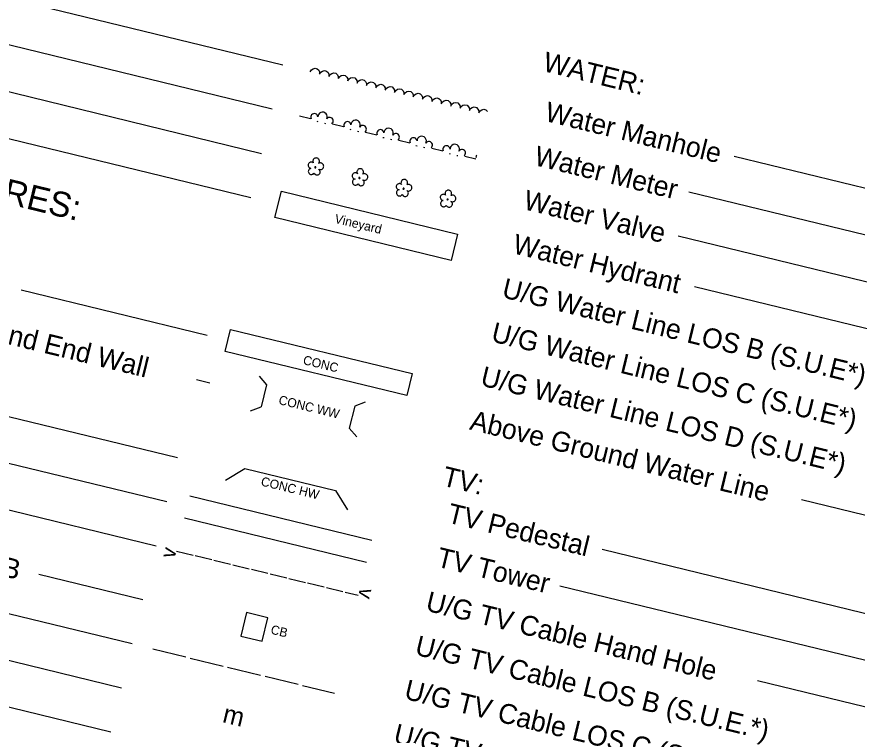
# Model space of a CAD drawing. Extents: x 1532568 to 1534465, y 472683 to 474150.
# Drawn here: x 1533832.3 to 1534202.9, y 473454 to 473770.7 of the extents above; entities that cross this region are included whole.
import ezdxf

# ---------------------------------------------------------------- set-up
doc = ezdxf.new("R2010")
doc.units = 0
doc.layers.add('Sheet Symbology CELL', color=7, linetype='Continuous')

msp = doc.modelspace()

# ---------------------------------------------------------------- linework, layer by layer
at = {"layer": 'Sheet Symbology CELL'}
for p, q in [((1533949.71, 473749.35), (1533743.06, 473799.65)), ((1533944.98, 473729.92), (1533769, 473772.75)), ((1533940.27, 473710.34), (1533741.14, 473758.81)), ((1533961.75, 473746.42), (1533962.27, 473747.27)), ((1533962.27, 473747.27), (1533963.01, 473747.76)), ((1533963.01, 473747.76), (1533963.89, 473748.01)), ((1533963.89, 473748.01), (1533964.81, 473747.79)), ((1533964.81, 473747.79), (1533965.47, 473747.11)), ((1533965.47, 473747.11), (1533965.85, 473746.35)), ((1533967.14, 473746.76), (1533968.02, 473747.01)), ((1533968.02, 473747.01), (1533968.94, 473746.78)), ((1533965.85, 473746.35), (1533965.85, 473745.48)), ((1533965.88, 473745.42), (1533966.4, 473746.27)), ((1533966.4, 473746.27), (1533967.14, 473746.76)), ((1533968.94, 473746.78), (1533969.6, 473746.11)), ((1533969.6, 473746.11), (1533969.98, 473745.34)), ((1533969.98, 473745.34), (1533969.97, 473744.47)), ((1533970.01, 473744.41), (1533970.53, 473745.26)), ((1533970.53, 473745.26), (1533971.26, 473745.75)), ((1533971.26, 473745.75), (1533972.15, 473746)), ((1533972.15, 473746), (1533973.07, 473745.78)), ((1533973.07, 473745.78), (1533973.73, 473745.1)), ((1533973.73, 473745.1), (1533974.11, 473744.34)), ((1533974.11, 473744.34), (1533974.1, 473743.47)), ((1533974.14, 473743.41), (1533974.66, 473744.26)), ((1533974.66, 473744.26), (1533975.39, 473744.75)), ((1533975.39, 473744.75), (1533976.28, 473745)), ((1533976.28, 473745), (1533977.2, 473744.77)), ((1533977.2, 473744.77), (1533977.86, 473744.1)), ((1533977.86, 473744.1), (1533978.24, 473743.33)), ((1533978.24, 473743.33), (1533978.23, 473742.46)), ((1533978.27, 473742.4), (1533978.79, 473743.25)), ((1533978.79, 473743.25), (1533979.52, 473743.74)), ((1533979.52, 473743.74), (1533980.41, 473743.99)), ((1533980.41, 473743.99), (1533981.33, 473743.77)), ((1533981.33, 473743.77), (1533981.99, 473743.09)), ((1533981.99, 473743.09), (1533982.37, 473742.33)), ((1533982.37, 473742.33), (1533982.36, 473741.46)), ((1533982.4, 473741.4), (1533982.92, 473742.25)), ((1533982.92, 473742.25), (1533983.65, 473742.74)), ((1533983.65, 473742.74), (1533984.54, 473742.98)), ((1533984.54, 473742.98), (1533985.46, 473742.76)), ((1533985.46, 473742.76), (1533986.12, 473742.09)), ((1533986.12, 473742.09), (1533986.5, 473741.32)), ((1533986.5, 473741.32), (1533986.49, 473740.45)), ((1533986.53, 473740.39), (1533987.05, 473741.24)), ((1533987.05, 473741.24), (1533987.78, 473741.73)), ((1533987.78, 473741.73), (1533988.67, 473741.98)), ((1533988.67, 473741.98), (1533989.59, 473741.76)), ((1533989.59, 473741.76), (1533990.25, 473741.08)), ((1533990.25, 473741.08), (1533990.63, 473740.32)), ((1533990.63, 473740.32), (1533990.62, 473739.45)), ((1533990.66, 473739.38), (1533991.18, 473740.24)), ((1533991.18, 473740.24), (1533991.91, 473740.73)), ((1533991.91, 473740.73), (1533992.8, 473740.97)), ((1533992.8, 473740.97), (1533993.72, 473740.75)), ((1533993.72, 473740.75), (1533994.38, 473740.07)), ((1533994.38, 473740.07), (1533994.76, 473739.31)), ((1533995.3, 473739.23), (1533996.04, 473739.72)), ((1533996.04, 473739.72), (1533996.92, 473739.97)), ((1533996.92, 473739.97), (1533997.85, 473739.74)), ((1533997.85, 473739.74), (1533998.51, 473739.07)), ((1533935.54, 473690.91), (1533736.41, 473739.38)), ((1533994.76, 473739.31), (1533994.75, 473738.44)), ((1533994.79, 473738.38), (1533995.3, 473739.23)), ((1533998.51, 473739.07), (1533998.89, 473738.31)), ((1533998.89, 473738.31), (1533998.88, 473737.43)), ((1533998.92, 473737.37), (1533999.43, 473738.23)), ((1533999.43, 473738.23), (1534000.17, 473738.72)), ((1534000.17, 473738.72), (1534001.05, 473738.96)), ((1534001.05, 473738.96), (1534001.98, 473738.74)), ((1534001.98, 473738.74), (1534002.64, 473738.06)), ((1534002.64, 473738.06), (1534003.02, 473737.3)), ((1534003.02, 473737.3), (1534003.01, 473736.43)), ((1534003.05, 473736.37), (1534003.56, 473737.22)), ((1534003.56, 473737.22), (1534004.3, 473737.71)), ((1534004.3, 473737.71), (1534005.18, 473737.96)), ((1534005.18, 473737.96), (1534006.11, 473737.73)), ((1534006.11, 473737.73), (1534006.77, 473737.06)), ((1534006.77, 473737.06), (1534007.15, 473736.3)), ((1534007.15, 473736.3), (1534007.14, 473735.42)), ((1534007.18, 473735.36), (1534007.69, 473736.22)), ((1534007.69, 473736.22), (1534008.43, 473736.71)), ((1534008.43, 473736.71), (1534009.31, 473736.95)), ((1534009.31, 473736.95), (1534010.24, 473736.73)), ((1534010.24, 473736.73), (1534010.9, 473736.05)), ((1534010.9, 473736.05), (1534011.28, 473735.29)), ((1534012.56, 473735.7), (1534013.44, 473735.95)), ((1534013.44, 473735.95), (1534014.37, 473735.72)), ((1534014.37, 473735.72), (1534015.02, 473735.05)), ((1534011.28, 473735.29), (1534011.27, 473734.42)), ((1534011.31, 473734.36), (1534011.82, 473735.21)), ((1534011.82, 473735.21), (1534012.56, 473735.7)), ((1534015.02, 473735.05), (1534015.41, 473734.29)), ((1534015.41, 473734.29), (1534015.4, 473733.41)), ((1534015.44, 473733.35), (1534015.95, 473734.21)), ((1534015.95, 473734.21), (1534016.69, 473734.7)), ((1534016.69, 473734.7), (1534017.57, 473734.94)), ((1534017.57, 473734.94), (1534018.5, 473734.72)), ((1534018.5, 473734.72), (1534019.15, 473734.04)), ((1534019.15, 473734.04), (1534019.53, 473733.28)), ((1534019.53, 473733.28), (1534019.53, 473732.41)), ((1534019.56, 473732.35), (1534020.08, 473733.2)), ((1534020.08, 473733.2), (1534020.82, 473733.69)), ((1534020.82, 473733.69), (1534021.7, 473733.94)), ((1534021.7, 473733.94), (1534022.62, 473733.71)), ((1534022.62, 473733.71), (1534023.28, 473733.04)), ((1534023.28, 473733.04), (1534023.66, 473732.28)), ((1534023.66, 473732.28), (1534023.66, 473731.4)), ((1534023.69, 473731.34), (1534024.21, 473732.2)), ((1534024.21, 473732.2), (1534024.95, 473732.69)), ((1534024.95, 473732.69), (1534025.83, 473732.93)), ((1534025.83, 473732.93), (1534026.75, 473732.71)), ((1534026.75, 473732.71), (1534027.41, 473732.03)), ((1534027.41, 473732.03), (1534027.79, 473731.27)), ((1534027.79, 473731.27), (1534027.79, 473730.4)), ((1534027.82, 473730.34), (1534028.34, 473731.19)), ((1534028.34, 473731.19), (1534029.08, 473731.68)), ((1534029.08, 473731.68), (1534029.96, 473731.93)), ((1534029.96, 473731.93), (1534030.88, 473731.7)), ((1534030.88, 473731.7), (1534031.54, 473731.03)), ((1534031.54, 473731.03), (1534031.92, 473730.27)), ((1534031.92, 473730.27), (1534031.92, 473729.39)), ((1534031.95, 473729.33), (1534032.47, 473730.19)), ((1534032.47, 473730.19), (1534033.21, 473730.68)), ((1534033.21, 473730.68), (1534034.09, 473730.92)), ((1534034.09, 473730.92), (1534035.01, 473730.7)), ((1534035.01, 473730.7), (1534035.67, 473730.02)), ((1534035.67, 473730.02), (1534036.05, 473729.26)), ((1534036.05, 473729.26), (1534036.05, 473728.39)), ((1534036.08, 473728.33), (1534036.6, 473729.18)), ((1534036.6, 473729.18), (1534037.34, 473729.67)), ((1534037.34, 473729.67), (1534038.22, 473729.92)), ((1534038.22, 473729.92), (1534039.14, 473729.69)), ((1534039.14, 473729.69), (1534039.8, 473729.02)), ((1534039.8, 473729.02), (1534039.84, 473728.96)), ((1533957.02, 473726.99), (1533961.88, 473725.81)), ((1533964.63, 473724.62), (1533965.11, 473724.5)), ((1533968.03, 473723.79), (1533968.52, 473723.68)), ((1533971.6, 473723.44), (1533976.46, 473722.26)), ((1533979.2, 473721.07), (1533979.69, 473720.96)), ((1533982.6, 473720.25), (1533983.09, 473720.13)), ((1533986.17, 473719.89), (1533991.03, 473718.71)), ((1533993.78, 473717.53), (1533994.26, 473717.41)), ((1533997.18, 473716.7), (1533997.66, 473716.58)), ((1534000.75, 473716.35), (1534005.6, 473715.16)), ((1534008.35, 473713.98), (1534008.84, 473713.86)), ((1534011.75, 473713.15), (1534012.24, 473713.03)), ((1534015.32, 473712.8), (1534020.18, 473711.62)), ((1534022.93, 473710.43), (1534023.41, 473710.31)), ((1534026.33, 473709.6), (1534026.81, 473709.49)), ((1534029.9, 473709.25), (1534034.75, 473708.07)), ((1534306.48, 473670.66), (1534148.7, 473709.07)), ((1534301.75, 473651.23), (1534128.76, 473693.34)), ((1534297.02, 473631.8), (1534124.03, 473673.9)), ((1534292.29, 473612.37), (1534131.21, 473651.57)), ((1533916.32, 473630.23), (1533834.29, 473650.19)), ((1533911.59, 473610.79), (1533917.41, 473609.38)), ((1533939.15, 473612.18), (1533942.46, 473608.43)), ((1533903.18, 473576.23), (1533778.52, 473606.57)), ((1533942.46, 473608.43), (1533940.1, 473598.71)), ((1533935.43, 473596.9), (1533940.1, 473598.71)), ((1533981.33, 473598.97), (1533978.96, 473589.25)), ((1533985.99, 473600.78), (1533981.33, 473598.97)), ((1533898.45, 473556.8), (1533733.09, 473597.05)), ((1533982.27, 473585.5), (1533978.96, 473589.25)), ((1533893.72, 473537.37), (1533715.45, 473580.76)), ((1533924.3, 473566.38), (1533932.85, 473571.58)), ((1533932.85, 473571.58), (1533972.93, 473561.83)), ((1533972.93, 473561.83), (1533978.13, 473553.28)), ((1533908.67, 473559.46), (1533988.83, 473539.95)), ((1534273.37, 473534.64), (1534178.43, 473557.74)), ((1533906.31, 473549.74), (1533986.47, 473530.23)), ((1534263.4, 473493.67), (1534090.41, 473535.78)), ((1533902.76, 473535.17), (1533910.05, 473533.39)), ((1533911.02, 473533.16), (1533918.3, 473531.38)), ((1533919.28, 473531.15), (1533926.56, 473529.37)), ((1533927.54, 473529.14), (1533934.82, 473527.36)), ((1533883.21, 473494.2), (1533750.15, 473526.59)), ((1533887.94, 473513.63), (1533842.08, 473524.79)), ((1533935.79, 473527.13), (1533943.08, 473525.35)), ((1533944.05, 473525.12), (1533951.34, 473523.34)), ((1533952.31, 473523.11), (1533959.6, 473521.33)), ((1533960.57, 473521.1), (1533967.86, 473519.32)), ((1533968.83, 473519.09), (1533976.12, 473517.31)), ((1533977.09, 473517.08), (1533982.92, 473515.66)), ((1534258.67, 473474.24), (1534071.79, 473519.73)), ((1533878.48, 473474.76), (1533766.09, 473502.12)), ((1533873.75, 473455.33), (1533714.21, 473494.16)), ((1533892.25, 473492), (1533906.83, 473488.45)), ((1533908.77, 473487.98), (1533923.34, 473484.43)), ((1533925.29, 473483.96), (1533939.86, 473480.41)), ((1533941.8, 473479.94), (1533956.38, 473476.39)), ((1534253.94, 473454.81), (1534159, 473477.91)), ((1533958.32, 473475.92), (1533972.41, 473472.49))]:
    msp.add_line(p, q, dxfattribs=at)
for points in [[(1533965.4, 473706.02), (1533965.62, 473706.28), (1533965.74, 473706.56), (1533965.76, 473706.86), (1533965.78, 473707.17), (1533965.7, 473707.45), (1533965.61, 473707.72), (1533965.41, 473707.98), (1533965.21, 473708.18), (1533964.89, 473708.36), (1533964.65, 473708.42), (1533964.34, 473708.44), (1533964.03, 473708.42), (1533963.75, 473708.33), (1533963.46, 473708.2), (1533963.24, 473707.94), (1533963.09, 473707.72), (1533962.97, 473707.44), (1533962.9, 473707.15), (1533962.87, 473706.85), (1533962.96, 473706.57), (1533963.08, 473706.23), (1533962.88, 473706.43), (1533962.6, 473706.55), (1533962.31, 473706.62), (1533962.04, 473706.59), (1533961.77, 473706.55), (1533961.48, 473706.41), (1533961.24, 473706.27), (1533961.04, 473706.06), (1533960.93, 473705.83), (1533960.8, 473705.5), (1533960.79, 473705.24), (1533960.82, 473704.98), (1533960.96, 473704.69), (1533961.06, 473704.46), (1533961.27, 473704.25), (1533961.52, 473704.04), (1533961.75, 473703.93), (1533962.04, 473703.86), (1533961.78, 473703.82), (1533961.49, 473703.68), (1533961.29, 473703.53), (1533961.13, 473703.26), (1533960.96, 473702.99), (1533960.9, 473702.75), (1533960.88, 473702.44), (1533960.96, 473702.17), (1533961.05, 473701.89), (1533961.2, 473701.65), (1533961.4, 473701.44), (1533961.62, 473701.28), (1533961.91, 473701.21), (1533962.21, 473701.14), (1533962.46, 473701.13), (1533962.75, 473701.27), (1533963.03, 473701.35), (1533963.38, 473701.73)], [(1533963.38, 473701.73), (1533963.88, 473701.25), (1533964.15, 473701.08), (1533964.43, 473700.96), (1533964.73, 473700.94), (1533965, 473700.98), (1533965.27, 473701.06), (1533965.57, 473701.2), (1533965.77, 473701.41), (1533965.93, 473701.63), (1533966.09, 473701.89), (1533966.12, 473702.2), (1533966.14, 473702.5), (1533966.02, 473702.84), (1533965.92, 473703.07), (1533965.71, 473703.27), (1533965.45, 473703.49), (1533965.73, 473703.37), (1533966.07, 473703.29), (1533966.34, 473703.33), (1533966.67, 473703.4), (1533966.95, 473703.49), (1533967.2, 473703.68), (1533967.42, 473703.94), (1533967.54, 473704.22), (1533967.65, 473704.5), (1533967.68, 473704.8), (1533967.65, 473705.12), (1533967.52, 473705.41), (1533967.33, 473705.71), (1533967.12, 473705.91), (1533966.86, 473706.08), (1533966.58, 473706.2), (1533966.29, 473706.27), (1533965.97, 473706.25), (1533965.69, 473706.16), (1533965.4, 473706.02)], [(1533964.16, 473704.53), (1533964.02, 473704.56), (1533963.91, 473704.54), (1533963.8, 473704.51), (1533963.76, 473704.37), (1533963.74, 473704.27), (1533963.81, 473704.15), (1533963.96, 473704.11), (1533964.06, 473704.09), (1533964.18, 473704.16), (1533964.26, 473704.3), (1533964.24, 473704.4), (1533964.16, 473704.53)], [(1533984.83, 473701.29), (1533985.05, 473701.55), (1533985.17, 473701.83), (1533985.19, 473702.13), (1533985.22, 473702.44), (1533985.13, 473702.72), (1533985.04, 473702.99), (1533984.85, 473703.25), (1533984.64, 473703.45), (1533984.32, 473703.63), (1533984.08, 473703.69), (1533983.78, 473703.71), (1533983.46, 473703.69), (1533983.18, 473703.6), (1533982.89, 473703.47), (1533982.68, 473703.21), (1533982.52, 473702.99), (1533982.4, 473702.71), (1533982.33, 473702.42), (1533982.31, 473702.12), (1533982.39, 473701.84), (1533982.52, 473701.5), (1533982.31, 473701.7), (1533982.03, 473701.82), (1533981.74, 473701.89), (1533981.47, 473701.86), (1533981.21, 473701.82), (1533980.91, 473701.68), (1533980.67, 473701.54), (1533980.47, 473701.33), (1533980.36, 473701.1), (1533980.23, 473700.77), (1533980.22, 473700.51), (1533980.26, 473700.25), (1533980.39, 473699.96), (1533980.49, 473699.73), (1533980.7, 473699.52), (1533980.95, 473699.31), (1533981.18, 473699.2), (1533981.48, 473699.13), (1533981.21, 473699.09), (1533980.92, 473698.95), (1533980.73, 473698.8), (1533980.56, 473698.53), (1533980.39, 473698.26), (1533980.33, 473698.02), (1533980.31, 473697.71), (1533980.4, 473697.44), (1533980.48, 473697.16), (1533980.63, 473696.92), (1533980.84, 473696.71), (1533981.06, 473696.55), (1533981.35, 473696.48), (1533981.64, 473696.41), (1533981.89, 473696.4), (1533982.18, 473696.54), (1533982.46, 473696.62), (1533982.81, 473697)], [(1533982.81, 473697), (1533983.31, 473696.52), (1533983.58, 473696.35), (1533983.86, 473696.23), (1533984.16, 473696.21), (1533984.43, 473696.25), (1533984.71, 473696.33), (1533985, 473696.47), (1533985.2, 473696.68), (1533985.36, 473696.9), (1533985.53, 473697.16), (1533985.55, 473697.47), (1533985.57, 473697.77), (1533985.45, 473698.11), (1533985.35, 473698.34), (1533985.14, 473698.54), (1533984.89, 473698.76), (1533985.17, 473698.64), (1533985.51, 473698.56), (1533985.77, 473698.6), (1533986.1, 473698.67), (1533986.38, 473698.76), (1533986.63, 473698.95), (1533986.85, 473699.21), (1533986.97, 473699.49), (1533987.09, 473699.77), (1533987.11, 473700.07), (1533987.08, 473700.39), (1533986.95, 473700.68), (1533986.76, 473700.98), (1533986.56, 473701.18), (1533986.29, 473701.35), (1533986.01, 473701.47), (1533985.72, 473701.54), (1533985.4, 473701.52), (1533985.12, 473701.43), (1533984.83, 473701.29)], [(1533983.59, 473699.8), (1533983.45, 473699.83), (1533983.34, 473699.81), (1533983.23, 473699.78), (1533983.2, 473699.64), (1533983.17, 473699.54), (1533983.25, 473699.42), (1533983.39, 473699.38), (1533983.49, 473699.36), (1533983.61, 473699.43), (1533983.69, 473699.57), (1533983.67, 473699.67), (1533983.59, 473699.8)], [(1534004.27, 473696.56), (1534004.48, 473696.82), (1534004.6, 473697.1), (1534004.63, 473697.4), (1534004.65, 473697.71), (1534004.56, 473697.99), (1534004.47, 473698.26), (1534004.28, 473698.52), (1534004.07, 473698.72), (1534003.76, 473698.9), (1534003.51, 473698.96), (1534003.21, 473698.98), (1534002.89, 473698.96), (1534002.62, 473698.87), (1534002.33, 473698.74), (1534002.11, 473698.48), (1534001.95, 473698.26), (1534001.83, 473697.98), (1534001.76, 473697.69), (1534001.74, 473697.39), (1534001.83, 473697.11), (1534001.95, 473696.77), (1534001.74, 473696.97), (1534001.46, 473697.09), (1534001.17, 473697.16), (1534000.9, 473697.13), (1534000.64, 473697.09), (1534000.35, 473696.95), (1534000.11, 473696.81), (1533999.9, 473696.6), (1533999.79, 473696.37), (1533999.66, 473696.04), (1533999.65, 473695.78), (1533999.69, 473695.52), (1533999.82, 473695.23), (1533999.92, 473695), (1534000.13, 473694.79), (1534000.39, 473694.58), (1534000.62, 473694.47), (1534000.91, 473694.4), (1534000.64, 473694.36), (1534000.35, 473694.22), (1534000.16, 473694.07), (1533999.99, 473693.8), (1533999.82, 473693.53), (1533999.76, 473693.29), (1533999.74, 473692.98), (1533999.83, 473692.71), (1533999.91, 473692.43), (1534000.06, 473692.19), (1534000.27, 473691.98), (1534000.49, 473691.82), (1534000.78, 473691.75), (1534001.07, 473691.68), (1534001.33, 473691.67), (1534001.62, 473691.81), (1534001.89, 473691.89), (1534002.24, 473692.27)], [(1534002.24, 473692.27), (1534002.74, 473691.79), (1534003.01, 473691.62), (1534003.29, 473691.5), (1534003.6, 473691.48), (1534003.86, 473691.52), (1534004.14, 473691.6), (1534004.43, 473691.74), (1534004.64, 473691.95), (1534004.79, 473692.17), (1534004.96, 473692.43), (1534004.98, 473692.74), (1534005, 473693.04), (1534004.88, 473693.38), (1534004.78, 473693.61), (1534004.58, 473693.81), (1534004.32, 473694.03), (1534004.6, 473693.91), (1534004.94, 473693.83), (1534005.21, 473693.87), (1534005.53, 473693.94), (1534005.81, 473694.03), (1534006.06, 473694.22), (1534006.28, 473694.48), (1534006.4, 473694.76), (1534006.52, 473695.04), (1534006.54, 473695.34), (1534006.52, 473695.66), (1534006.38, 473695.95), (1534006.2, 473696.25), (1534005.99, 473696.45), (1534005.72, 473696.62), (1534005.44, 473696.74), (1534005.15, 473696.81), (1534004.84, 473696.79), (1534004.56, 473696.7), (1534004.27, 473696.56)], [(1534003.03, 473695.07), (1534002.88, 473695.1), (1534002.77, 473695.08), (1534002.66, 473695.05), (1534002.63, 473694.91), (1534002.6, 473694.81), (1534002.68, 473694.69), (1534002.82, 473694.65), (1534002.92, 473694.63), (1534003.04, 473694.7), (1534003.13, 473694.84), (1534003.1, 473694.94), (1534003.03, 473695.07)], [(1533949, 473693.81), (1534026.73, 473674.89), (1534023.89, 473663.23), (1533946.16, 473682.15), (1533949, 473693.81)], [(1534023.7, 473691.83), (1534023.92, 473692.09), (1534024.04, 473692.37), (1534024.06, 473692.67), (1534024.08, 473692.98), (1534023.99, 473693.26), (1534023.91, 473693.53), (1534023.71, 473693.79), (1534023.5, 473693.99), (1534023.19, 473694.17), (1534022.94, 473694.23), (1534022.64, 473694.25), (1534022.33, 473694.23), (1534022.05, 473694.14), (1534021.76, 473694.01), (1534021.54, 473693.75), (1534021.38, 473693.53), (1534021.27, 473693.25), (1534021.19, 473692.96), (1534021.17, 473692.66), (1534021.26, 473692.38), (1534021.38, 473692.04), (1534021.17, 473692.24), (1534020.89, 473692.36), (1534020.6, 473692.43), (1534020.34, 473692.4), (1534020.07, 473692.36), (1534019.78, 473692.22), (1534019.54, 473692.08), (1534019.33, 473691.87), (1534019.23, 473691.64), (1534019.09, 473691.31), (1534019.08, 473691.05), (1534019.12, 473690.79), (1534019.26, 473690.5), (1534019.36, 473690.27), (1534019.56, 473690.06), (1534019.82, 473689.85), (1534020.05, 473689.74), (1534020.34, 473689.67), (1534020.08, 473689.63), (1534019.78, 473689.49), (1534019.59, 473689.34), (1534019.42, 473689.07), (1534019.26, 473688.8), (1534019.2, 473688.56), (1534019.17, 473688.25), (1534019.26, 473687.98), (1534019.35, 473687.7), (1534019.49, 473687.46), (1534019.7, 473687.25), (1534019.92, 473687.09), (1534020.21, 473687.02), (1534020.5, 473686.95), (1534020.76, 473686.94), (1534021.05, 473687.08), (1534021.33, 473687.16), (1534021.68, 473687.54)], [(1534021.68, 473687.54), (1534022.18, 473687.06), (1534022.44, 473686.89), (1534022.72, 473686.77), (1534023.03, 473686.75), (1534023.29, 473686.79), (1534023.57, 473686.87), (1534023.86, 473687.01), (1534024.07, 473687.22), (1534024.22, 473687.44), (1534024.39, 473687.7), (1534024.41, 473688.01), (1534024.44, 473688.31), (1534024.31, 473688.65), (1534024.22, 473688.88), (1534024.01, 473689.08), (1534023.75, 473689.3), (1534024.03, 473689.18), (1534024.37, 473689.1), (1534024.64, 473689.14), (1534024.96, 473689.21), (1534025.24, 473689.3), (1534025.5, 473689.49), (1534025.71, 473689.75), (1534025.83, 473690.03), (1534025.95, 473690.31), (1534025.97, 473690.61), (1534025.95, 473690.93), (1534025.81, 473691.22), (1534025.63, 473691.52), (1534025.42, 473691.72), (1534025.15, 473691.89), (1534024.87, 473692.01), (1534024.58, 473692.08), (1534024.27, 473692.06), (1534023.99, 473691.97), (1534023.7, 473691.83)], [(1534022.46, 473690.34), (1534022.31, 473690.37), (1534022.21, 473690.35), (1534022.1, 473690.32), (1534022.06, 473690.18), (1534022.04, 473690.08), (1534022.11, 473689.96), (1534022.26, 473689.92), (1534022.35, 473689.9), (1534022.47, 473689.97), (1534022.56, 473690.11), (1534022.53, 473690.21), (1534022.46, 473690.34)], [(1533926.54, 473632.88), (1534006.7, 473613.37), (1534004.34, 473603.66), (1533924.18, 473623.17), (1533926.54, 473632.88)]]:
    msp.add_lwpolyline(points, dxfattribs=at)
msp.add_lwpolyline([(1533931.13, 473497.65), (1533940.47, 473495.38), (1533942.98, 473505.71), (1533933.64, 473507.99)], close=True, dxfattribs=at)
for centre, radius, start, end in [((1533967.17, 473726.59), 2.06, 332.2837, 180.3562), ((1533963.53, 473726.45), 1.58, 4.7549, 205.5515), ((1533970.33, 473724.79), 1.58, 307.0885, 147.885), ((1533981.74, 473723.05), 2.06, 332.2837, 180.3562), ((1533978.1, 473722.9), 1.58, 4.7549, 205.5515), ((1533984.9, 473721.25), 1.58, 307.0885, 147.885), ((1533992.68, 473719.35), 1.58, 4.7549, 205.5515), ((1533996.31, 473719.5), 2.06, 332.2837, 180.3562), ((1533999.48, 473717.7), 1.58, 307.0885, 147.885), ((1534007.25, 473715.81), 1.58, 4.7549, 205.5515), ((1534010.89, 473715.95), 2.06, 332.2837, 180.3562), ((1534014.05, 473714.15), 1.58, 307.0885, 147.885), ((1534021.83, 473712.26), 1.58, 4.7549, 205.5515), ((1534025.46, 473712.4), 2.06, 332.2837, 180.3562), ((1534028.63, 473710.6), 1.58, 307.0885, 147.885), ((1534036.4, 473708.71), 1.58, 142.571, 190.069)]:
    msp.add_arc(centre, radius, start, end, dxfattribs=at)

# ---------------------------------------------------------------- texts
for s, height, rotation, p in [('WATER:', 8.75, 346.32, (1534063.87, 473746.87)), ('EXISTING STRUCTURES:', 11, 346.32, (1533686.7, 473722.6)), ('Water Manhole', 8.75, 346.32, (1534064.74, 473724.84)), ('Water Meter', 8.75, 346.32, (1534060.01, 473705.4)), ('Water Valve', 8.75, 346.32, (1534055.28, 473685.97)), ('Vineyard', 4, 346.32, (1533972.2, 473679.93)), ('Water Hydrant', 8.75, 346.32, (1534050.55, 473666.54)), ('Bridge Wing Wall, Head Wall and End Wall', 8.75, 346.32, (1533672.51, 473664.31)), ('U/G Water Line LOS B (S.U.E*)', 8.75, 346.32, (1534045.82, 473647.11)), ('U/G Water Line LOS C (S.U.E*)', 8.75, 346.32, (1534041.09, 473627.67)), ('CONC', 4, 346.32, (1533958.26, 473617.59)), ('U/G Water Line LOS D (S.U.E*)', 8.75, 346.32, (1534036.36, 473608.24)), ('CONC WW', 4, 346.32, (1533947.49, 473600)), ('Above Ground Water Line', 8.75, 346.32, (1534031.63, 473588.81)), ('Drainage Box: Catch Basin, DI or JB', 8.75, 346.32, (1533648.87, 473567.15)), ('TV:', 8.75, 346.32, (1534019.39, 473564.12)), ('CONC HW', 4, 346.32, (1533939.7, 473564.09)), ('TV Pedestal', 8.75, 346.32, (1534021.65, 473547.84)), ('v', 6.6, 76.0791, (1533901.86, 473531.54)), ('TV Tower', 8.75, 346.32, (1534016.92, 473528.41)), ('v', 6.6, 256.5608, (1533983.79, 473519.29)), ('U/G TV Cable Hand Hole', 8.75, 346.32, (1534012.19, 473508.98)), ('CB', 4, 346.32, (1533944.01, 473498.77)), ('U/G TV Cable LOS B (S.U.E.*)', 8.75, 346.32, (1534007.46, 473489.54)), ('U/G TV Cable LOS C (S.U.E.*)', 8.75, 346.32, (1534002.73, 473470.11)), ('m', 8.25, 346.32, (1533922.62, 473459.78)), ('U/G TV Cable LOS D (S.U.E.*)', 8.75, 346.32, (1533998, 473450.68))]:
    msp.add_text(s, height=height, rotation=rotation, dxfattribs=at).set_placement(p)

doc.saveas('drawing.dxf')
